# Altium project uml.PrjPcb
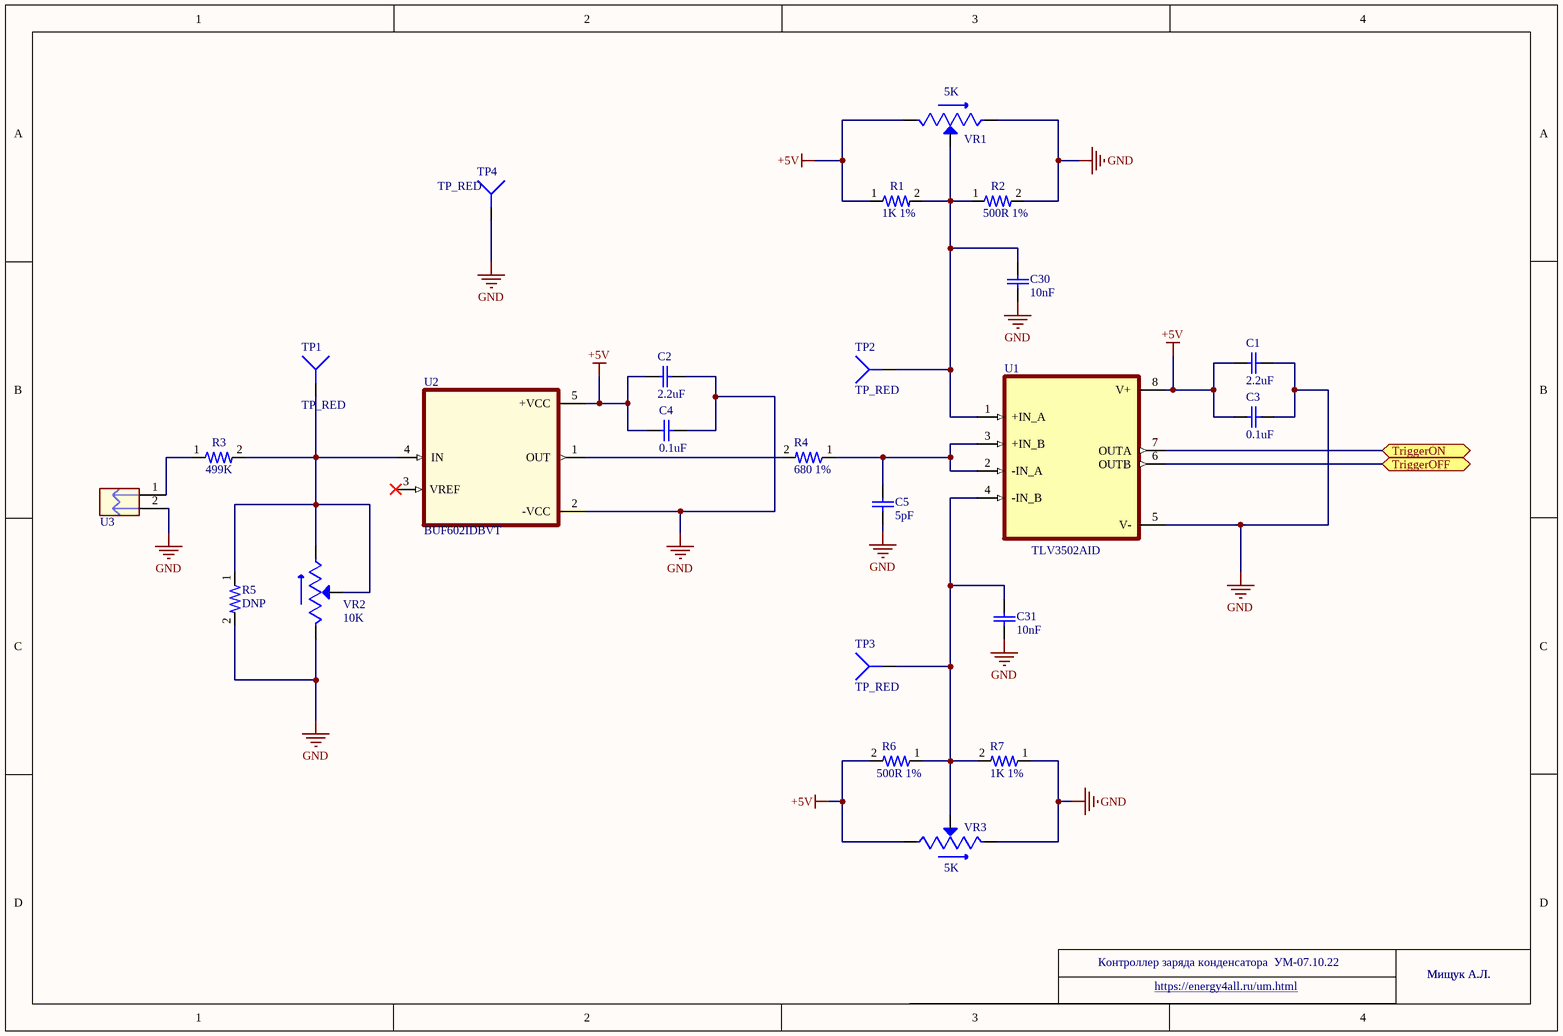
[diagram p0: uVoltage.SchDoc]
6 sheets, 99 parts. Net scope: flat (ports and power ports of the same name join across sheets).
Board file: uml.PcbDoc
Sheets:
  uVoltage.SchDoc
  lockgen.SchDoc
  lock.SchDoc
  uDelay.SchDoc
  uPower.SchDoc
  uSupply.SchDoc

## Sheet uVoltage.SchDoc
size A4; SheetNumber: 1; SheetTotal: 7

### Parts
C1  2.2uF  [CAP_0603]
C2  2.2uF  [CAP_0603]
C3  0.1uF  [CAP_0603]
C4  0.1uF  [CAP_0603]
C5  5pF  [CAP_0603]
C30  10nF  [CAP_0603]
C31  10nF  [CAP_0603]
R1  1K 1%  [RESC1608X50N]
R2  500R 1%  [RESC1608X50N]
R3  499K  [RES_2512]
R4  680 1%  [RESC1608X50N]
R5  DNP  [RESC1608X50N]
R6  500R 1%  [RESC1608X50N]
R7  1K 1%  [RESC1608X50N]
TP1  TP_RED  [TP_RED]
TP2  TP_RED  [TP_RED]
TP3  TP_RED  [TP_RED]
TP4  TP_RED  [TP_RED]
U1  TLV3502AID  [TLV3502AID]
U2  BUF602IDBVT  [BUF602IDBVT]
U3  DG129-5.0-02P  [DG129-5.0-02P]  (value not drawn)
VR1  5K  [TRIM_3296W-1-250]
VR2  10K  [TRIM_3296W-1-250]
VR3  5K  [TRIM_3296W-1-250]

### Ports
TriggerOFF (bidir), TriggerON (bidir)

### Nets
+5V: C1.1 C2.1 C3.1 C4.1 R1.1 R6.2 U1.8(V+) U2.5(+VCC) VR1.1(CCW) VR3.1(CCW)
GND: C1.2 C2.2 C3.2 C4.2 C5.2 C30.2 C31.2 R2.2 R5.2 R7.1 TP4.1 U1.5(V-) U2.2(-VCC) U3.2 VR1.3(CW) VR2.1(CCW) VR3.3(CW)
NetC5_1: C5.1 R4.1 U1.2(-IN_A) U1.3(+IN_B)
NetC30_1: C30.1 R1.2 R2.1 TP2.1 U1.1(+IN_A) VR1.2(WIPER)
NetC31_1: C31.1 R6.1 R7.2 TP3.1 U1.4(-IN_B) VR3.2(WIPER)
NetR3_1: R3.1 U3.1
NetR3_2: R3.2 R5.1 TP1.1 U2.4(IN) VR2.2(WIPER) VR2.3(CW)
NetR4_2: R4.2 U2.1(OUT)
NetU1_6: U1.6(OUTB) ; port TriggerOFF
NetU1_7: U1.7(OUTA) ; port TriggerON

Not connected (* = marked no-connect by the designer): U2 3(VREF)*

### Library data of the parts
C1-C5 C30 C31 = CAP_0603
R1 R2 R4-R7 = RES_0603: 1% 0.1W; MP: 1-2176071-4
R3 = RES_2512: 2512 1% 1W; MP: 1-2176071-4
TP1-TP4 = TP_RED: RF EMI Absorbing Sheet - Polyurethane Foam 24.000 (609.60mm) X 24.000 (609.60mm) X 0.252 (6.40mm); MF: Aeroflex; MP: 5010
U1 = TLV3502AID: 4.5ns Rail-to-Rail Comparator; MF: Texas Instruments
U2 = BUF602IDBVT: 1000MHz,Wide Bandwidth, High-Speed, Closed Loop Buffer 5-SOT-23 -45 to 85; MF: Texas Instruments
U3 = DG129-5.0-02P: DG129-5.0-02P-14-00A(H)
VR1-VR3 = 3296W-1-250: 25 Ohms 0.5W, 1/2W PC Pins Through Hole Trimmer Potentiometer Cermet 25 Turn Top Adjustment; MF: Bourns

## Sheet lockgen.SchDoc
size A4; Organization: Altium Limited; Address1: L3, 12a Rodborough Rd; Address2: Frenchs Forest; Address3: NSW; Address4: Australia 2086
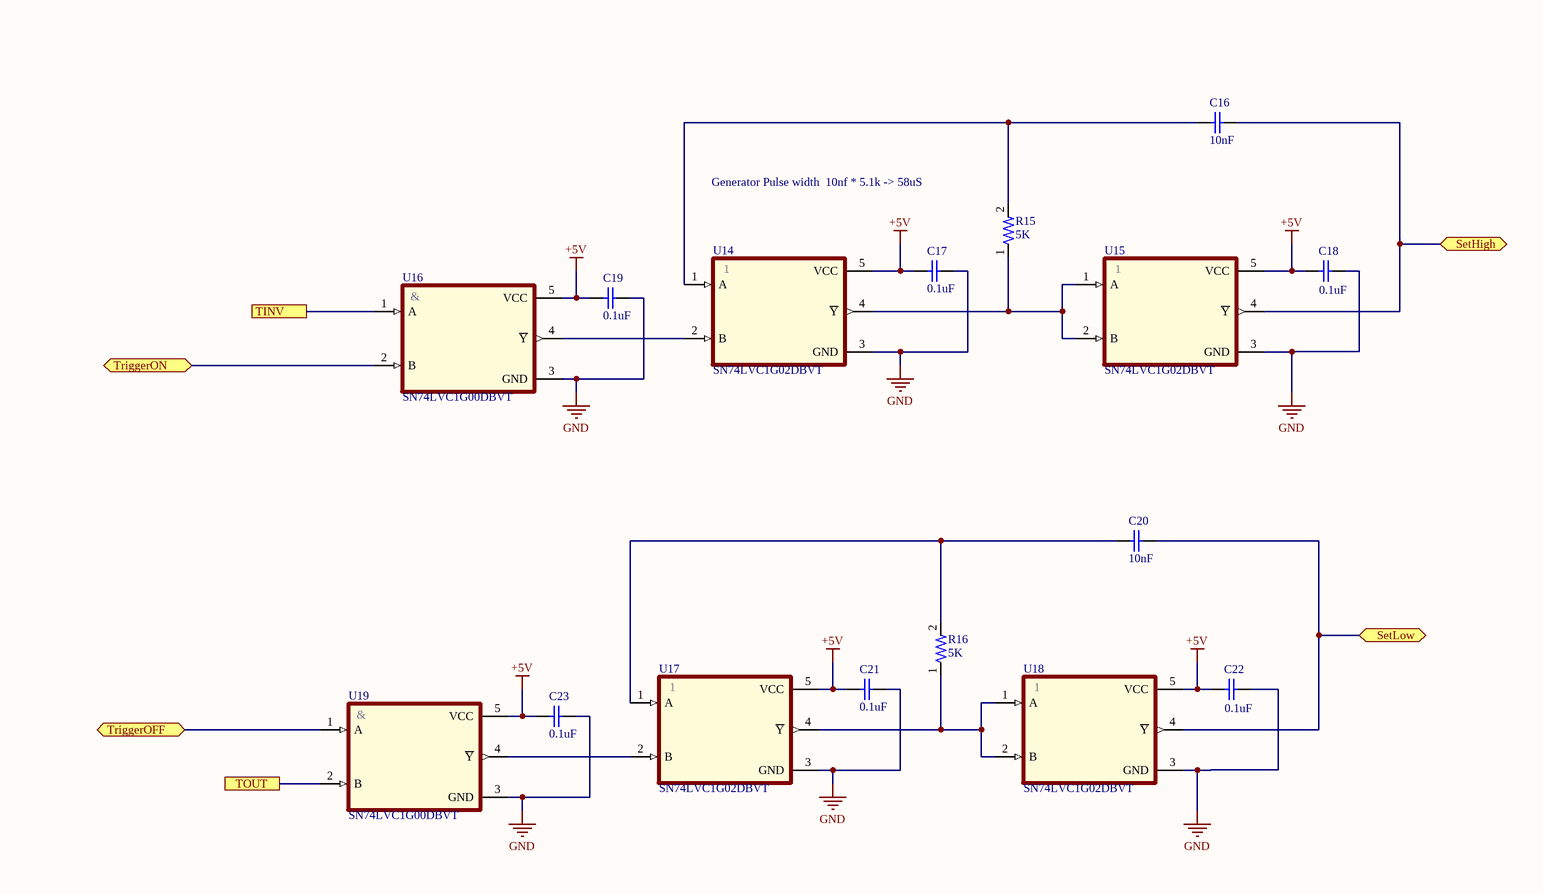
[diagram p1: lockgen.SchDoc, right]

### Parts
C16  10nF  [CAP_0603]
C17  0.1uF  [CAP_0603]
C18  0.1uF  [CAP_0603]
C19  0.1uF  [CAP_0603]
C20  10nF  [CAP_0603]
C21  0.1uF  [CAP_0603]
C22  0.1uF  [CAP_0603]
C23  0.1uF  [CAP_0603]
R15  5K  [RESC1608X50N]
R16  5K  [RESC1608X50N]
U14  SN74LVC1G02DBVT  [SOT23-5]
U15  SN74LVC1G02DBVT  [SOT23-5]
U16  SN74LVC1G00DBVT  [SOT23-5]
U17  SN74LVC1G02DBVT  [SOT23-5]
U18  SN74LVC1G02DBVT  [SOT23-5]
U19  SN74LVC1G00DBVT  [SOT23-5]

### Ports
SetHigh (bidir), SetLow (bidir), TINV, TOUT, TriggerOFF (bidir), TriggerON (bidir)

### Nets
+5V: C17.2 C18.2 C19.2 C21.2 C22.2 C23.2 U14.5(VCC) U15.5(VCC) U16.5(VCC) U17.5(VCC) U18.5(VCC) U19.5(VCC)
GND: C17.1 C18.1 C19.1 C21.1 C22.1 C23.1 U14.3(GND) U15.3(GND) U16.3(GND) U17.3(GND) U18.3(GND) U19.3(GND)
NetC16_1: C16.1 R15.2 U14.1(A)
NetC16_2: C16.2 U15.4(~{Y}) ; port SetHigh
NetC20_1: C20.1 R16.2 U17.1(A)
NetC20_2: C20.2 U18.4(~{Y}) ; port SetLow
NetJP4_3: U19.2(B) ; port TOUT
NetJP5_1: U16.1(A) ; port TINV
NetR15_1: R15.1 U14.4(~{Y}) U15.1(A) U15.2(B)
NetR16_1: R16.1 U17.4(~{Y}) U18.1(A) U18.2(B)
NetU1_6: U19.1(A) ; port TriggerOFF
NetU1_7: U16.2(B) ; port TriggerON
NetU14_2: U14.2(B) U16.4(~{Y})
NetU17_2: U17.2(B) U19.4(~{Y})

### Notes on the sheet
- (near R15) Generator Pulse width  10nf * 5.1k -> 58uS

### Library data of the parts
C16-C23 = CAP_0603
R15 R16 = RES_0603: 1% 0.1W; MP: 1-2176071-4
U14 U15 U17 U18 = SN74LVC1G02DBVT: NOR IC 1 canal SOT-23-5; MF: Texas Instruments
U16 U19 = SN74LVC1G00DBVT: NAND IC 1 canal SOT-23-5; MF: Texas Instruments

## Sheet lock.SchDoc
size A4; Organization: Altium Limited; Address1: L3, 12a Rodborough Rd; Address2: Frenchs Forest; Address3: NSW; Address4: Australia 2086
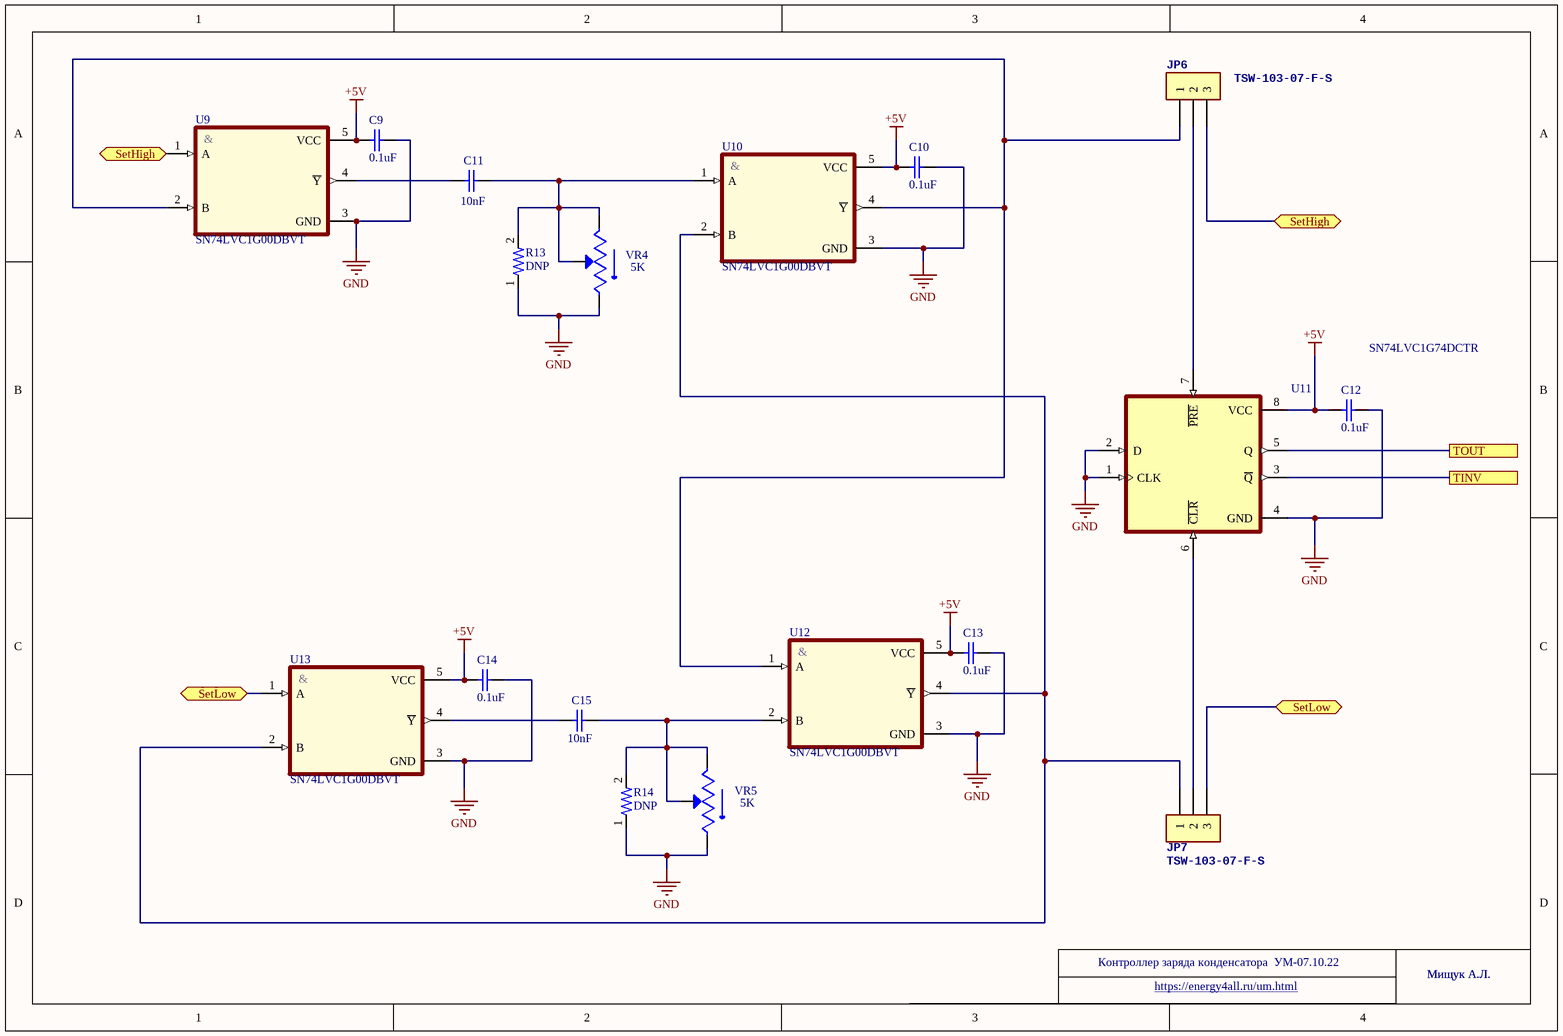
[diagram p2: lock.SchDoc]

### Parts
C9  0.1uF  [CAP_0603]
C10  0.1uF  [CAP_0603]
C11  10nF  [CAP_0603]
C12  0.1uF  [CAP_0603]
C13  0.1uF  [CAP_0603]
C14  0.1uF  [CAP_0603]
C15  10nF  [CAP_0603]
JP6  TSW-103-07-F-S  [TSW-103-07-F-S]
JP7  TSW-103-07-F-S  [TSW-103-07-F-S]
R13  DNP  [RESC1608X50N]
R14  DNP  [RESC1608X50N]
U9  SN74LVC1G00DBVT  [SOT23-5]
U10  SN74LVC1G00DBVT  [SOT23-5]
U11  SN74LVC1G74DCTR  [SN74LVC1G74DCTR]
U12  SN74LVC1G00DBVT  [SOT23-5]
U13  SN74LVC1G00DBVT  [SOT23-5]
VR4  5K  [TRIM_3296W-1-250]
VR5  5K  [TRIM_3296W-1-250]

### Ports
SetHigh (bidir), SetLow (bidir), TINV, TOUT

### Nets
+5V: C9.2 C10.2 C12.2 C13.2 C14.2 U9.5(VCC) U10.5(VCC) U11.8(VCC) U12.5(VCC) U13.5(VCC)
GND: C9.1 C10.1 C12.1 C13.1 C14.1 R13.1 R14.1 U9.3(GND) U10.3(GND) U11.1(CLK) U11.2(D) U11.4(GND) U12.3(GND) U13.3(GND) VR4.3(CW) VR5.3(CW)
NetC11_1: C11.1 R13.2 U10.1(A) VR4.1(CCW) VR4.2(WIPER)
NetC11_2: C11.2 U9.4(~{Y})
NetC15_1: C15.1 R14.2 U12.2(B) VR5.1(CCW) VR5.2(WIPER)
NetC15_2: C15.2 U13.4(~{Y})
NetC16_2: JP6.3 U9.1(A) ; port SetHigh
NetC20_2: JP7.3 U13.1(A) ; port SetLow
NetJP4_3: U11.5(Q) ; port TOUT
NetJP5_1: U11.3(~{Q}) ; port TINV
NetJP6_1: JP6.1 U9.2(B) U10.4(~{Y}) U12.1(A)
NetJP6_2: JP6.2 U11.7(~{PRE})
NetJP7_1: JP7.1 U10.2(B) U12.4(~{Y}) U13.2(B)
NetJP7_2: JP7.2 U11.6(~{CLR})

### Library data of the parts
C9-C15 = CAP_0603
R13 R14 = RES_0603: 1% 0.1W; MP: 1-2176071-4
U9 U10 U12 U13 = SN74LVC1G00DBVT: as U16 on sheet lockgen
U11 = SN74LVC1G74DCTR: Single Positive-Edge-Triggered D-Type Flip-Flop With Clear and Preset 8-SM8 -40 to 125; MF: Texas Instruments
VR4 VR5 = 3296W-1-250: as VR1 on sheet uVoltage

## Sheet uDelay.SchDoc
size A4; SheetNumber: 1; SheetTotal: 7
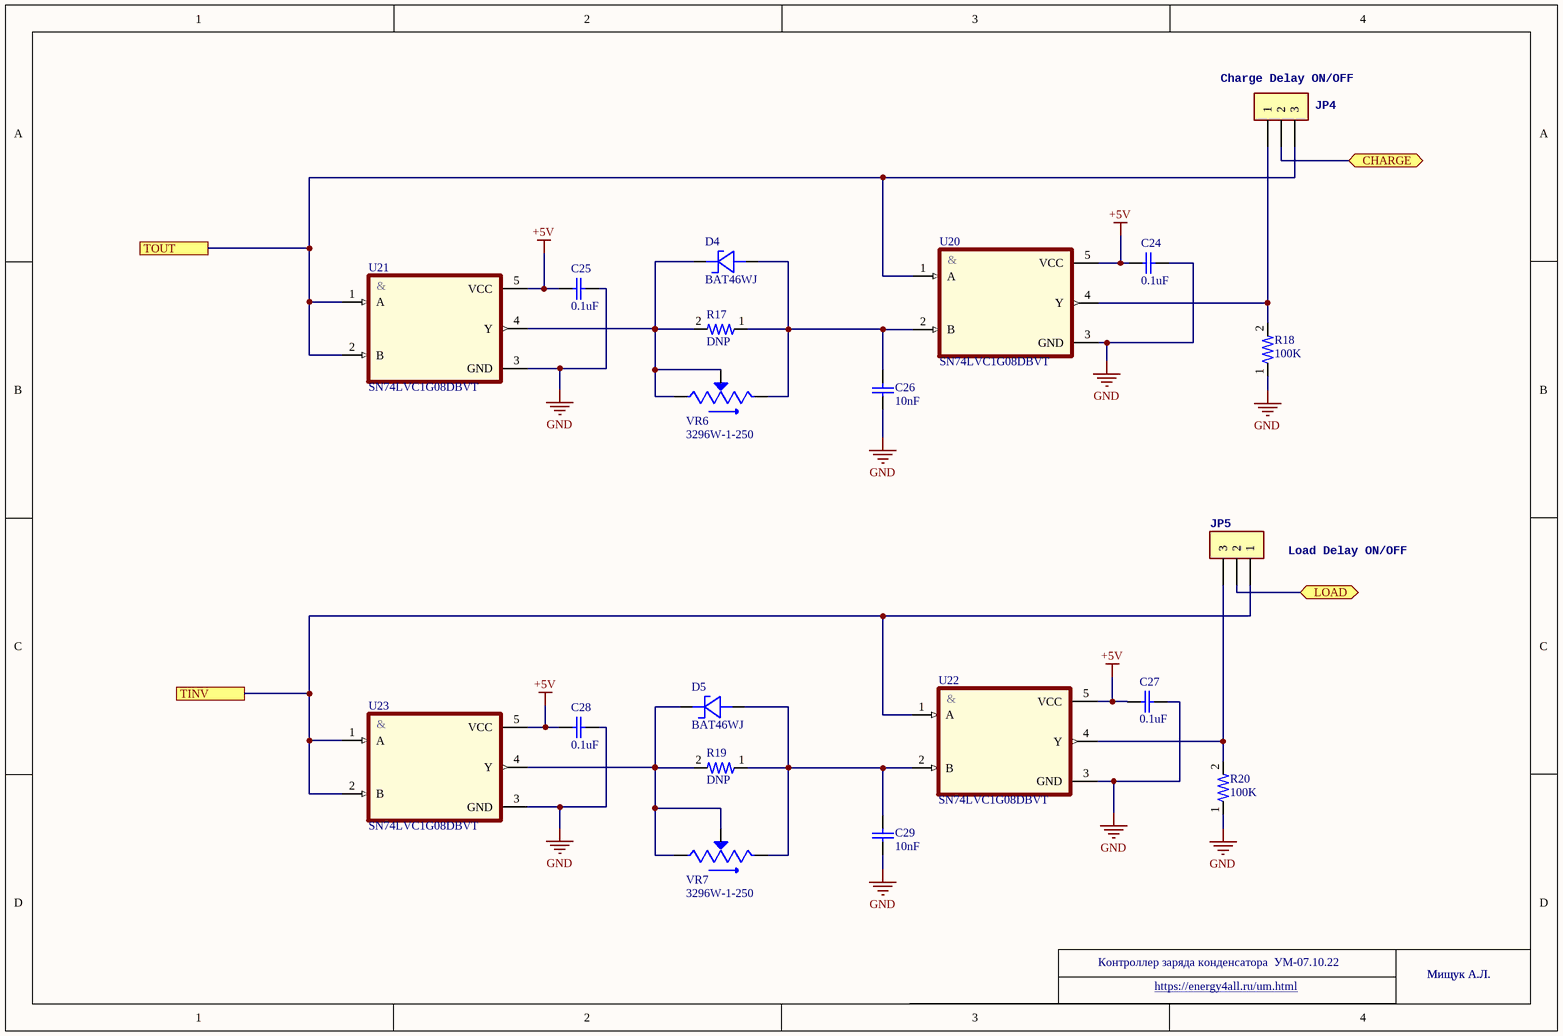
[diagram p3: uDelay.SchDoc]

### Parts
C24  0.1uF  [CAP_0603]
C25  0.1uF  [CAP_0603]
C26  10nF  [CAP_0805]
C27  0.1uF  [CAP_0603]
C28  0.1uF  [CAP_0603]
C29  10nF  [CAP_0805]
D4  BAT46WJ  [BAT46WJ]
D5  BAT46WJ  [BAT46WJ]
JP4  Charge Delay ON/OFF  [TSW-103-07-F-S]
JP5  Load Delay ON/OFF  [TSW-103-07-F-S]
R17  DNP  [RESC1608X50N]
R18  100K  [RESC1608X50N]
R19  DNP  [RESC1608X50N]
R20  100K  [RESC1608X50N]
U20  SN74LVC1G08DBVT  [SOT23-5]
U21  SN74LVC1G08DBVT  [SOT23-5]
U22  SN74LVC1G08DBVT  [SOT23-5]
U23  SN74LVC1G08DBVT  [SOT23-5]
VR6  3296W-1-250  [TRIM_3296W-1-250]
VR7  3296W-1-250  [TRIM_3296W-1-250]

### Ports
CHARGE (bidir), LOAD (bidir), TINV, TOUT

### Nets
+5V: C24.1 C25.1 C27.1 C28.1 U20.5(VCC) U21.5(VCC) U22.5(VCC) U23.5(VCC)
GND: C24.2 C25.2 C26.1 C27.2 C28.2 C29.1 R18.1 R20.1 U20.3(GND) U21.3(GND) U22.3(GND) U23.3(GND)
NetC26_2: C26.2 D4.A R17.1 U20.2(B) VR6.3(CW)
NetC29_2: C29.2 D5.A R19.1 U22.2(B) VR7.3(CW)
NetD4_C: D4.C R17.2 U21.4(Y) VR6.1(CCW) VR6.2(WIPER)
NetD5_C: D5.C R19.2 U23.4(Y) VR7.1(CCW) VR7.2(WIPER)
NetJP2_1: JP4.2 ; port CHARGE
NetJP3_1: JP5.2 ; port LOAD
NetJP4_1: JP4.1 R18.2 U20.4(Y)
NetJP4_3: JP4.3 U20.1(A) U21.1(A) U21.2(B) ; port TOUT
NetJP5_1: JP5.1 U22.1(A) U23.1(A) U23.2(B) ; port TINV
NetJP5_3: JP5.3 R20.2 U22.4(Y)

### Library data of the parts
C24 C25 C27 C28 = CAP_0603
C26 C29 = CAP_0805
D4 D5 = BAT46WJ: Diode Schottky 100V 250mA (DC) Surface Mount SOD-323F; MF: NXP Semiconductors
JP4 JP5 = TSW-103-07-F-S
R17-R20 = RES_0603: 1% 0.1W; MP: 1-2176071-4
U20-U23 = SN74LVC1G08DBVT: AND IC 1 chanal SOT-23-5; MF: Texas Instruments
VR6 VR7 = 3296W-1-250: as VR1 on sheet uVoltage

## Sheet uPower.SchDoc
size A4; SheetNumber: 1; SheetTotal: 7
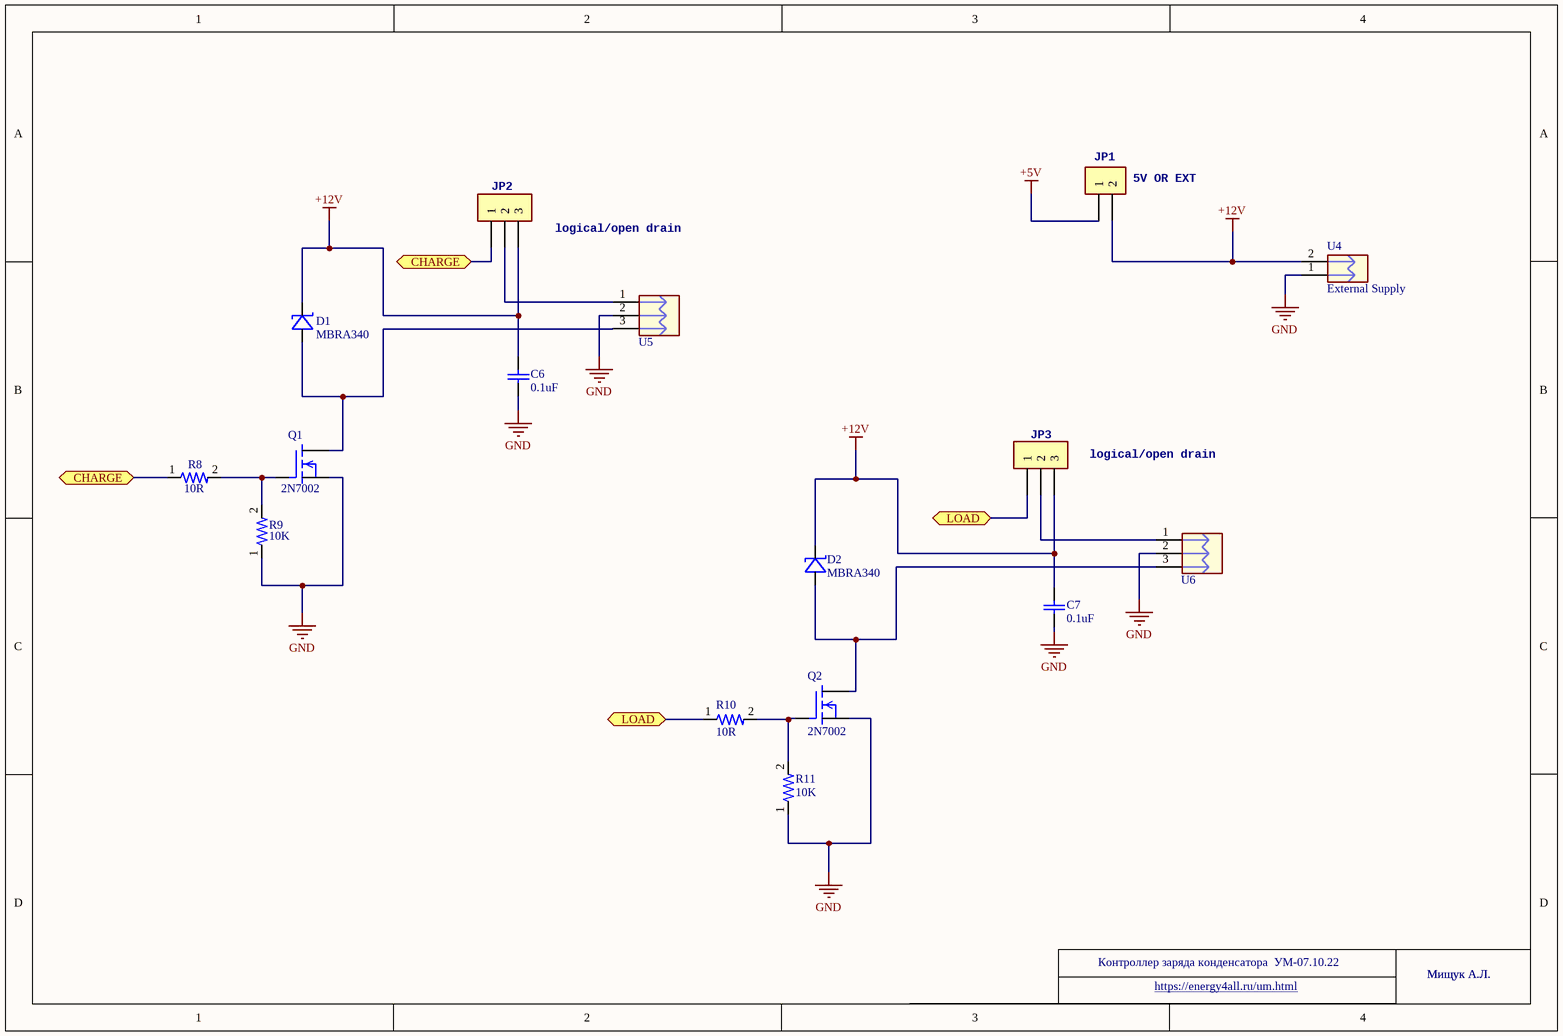
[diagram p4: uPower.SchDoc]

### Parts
C6  0.1uF  [CAP_1206]
C7  0.1uF  [CAP_1206]
D1  MBRA340  [MBRA340]
D2  MBRA340  [MBRA340]
JP1  5V OR EXT  [TSW-102-07-F-S]
JP2  logical/open drain  [TSW-103-07-F-S]
JP3  logical/open drain  [TSW-103-07-F-S]
Q1  2N7002  [2N7002]
Q2  2N7002  [2N7002]
R8  10R  [RESC1608X50N]
R9  10K  [RESC1608X50N]
R10  10R  [RESC1608X50N]
R11  10K  [RESC1608X50N]
U4  External Supply  [DG129-5.0-02P]
U5  DG129-5.0-03P  [DG129-5.0-03P]  (value not drawn)
U6  DG129-5.0-03P  [DG129-5.0-03P]  (value not drawn)

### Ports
CHARGE (bidir), LOAD (bidir)

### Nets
+5V: JP1.1
+12V: C6.2 C7.2 D1.C D2.C JP1.2 JP2.3 JP3.3 U4.2
GND: C6.1 C7.1 Q1.2(S) Q2.2(S) R9.1 R11.1 U4.1 U5.2 U6.2
NetD1_A: D1.A Q1.3(D) U5.3
NetD2_A: D2.A Q2.3(D) U6.3
NetJP2_1: JP2.1 R8.1 ; port CHARGE
NetJP2_2: JP2.2 U5.1
NetJP3_1: JP3.1 R10.1 ; port LOAD
NetJP3_2: JP3.2 U6.1
NetQ1_1: Q1.1(G) R8.2 R9.2
NetQ2_1: Q2.1(G) R10.2 R11.2

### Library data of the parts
C6 C7 = CAP_1206
D1 D2 = MBRA340: DIODE, SCHOTTKY, 3A, 40V, SMA; MF: ON Semiconductor
JP1 = TSW-102-07-F-S
JP2 JP3 = TSW-103-07-F-S
Q1 Q2 = 2N7002: N-Channel 60V 200mA _Tc_ 350mW _Tc_ Surface Mount SOT-23-3; MF: STMicroelectronics
R8-R11 = RES_0603: 1% 0.1W; MP: 1-2176071-4
U4 = DG129-5.0-02P: DG129-5.0-02P-14-00A(H)
U5 U6 = DG129-5.0-03P: DG129-5.0-03P-14-00AH

## Sheet uSupply.SchDoc
size A4; SheetNumber: 1; SheetTotal: 7
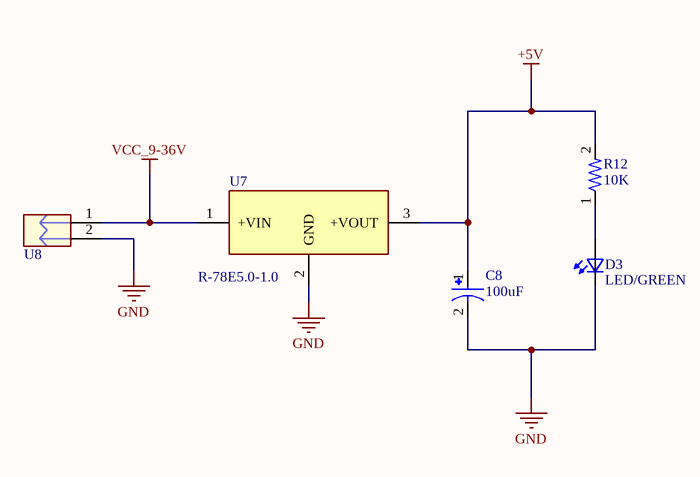
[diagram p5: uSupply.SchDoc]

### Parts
C8  100uF  [CAP_TYPE_D]
D3  LED/GREEN  [LED_0603]
R12  10K  [RESC1608X50N]
U7  R-78E5.0-1.0  [R-78E5.0-1.0]
U8  DG129-5.0-02P  [DG129-5.0-02P]  (value not drawn)

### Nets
+5V: C8.1 R12.2 U7.3(+VOUT)
GND: C8.2 D3.1(K1) U7.2(GND) U8.2
VCC_9-36V: U7.1(+VIN) U8.1
NetD3_2: D3.2(A2) R12.1

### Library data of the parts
C8 = CAP_TYPE_D: MP: 25TQC15MV
D3 = LED_0603: Blue 470nm LED Indication - Discrete 3.3V 0603 _1608 Metric_; MP: LTST-S270TBKT; MF: Lite-On Inc.
R12 = RES_0603: 1% 0.1W; MP: 1-2176071-4
U7 = R-78E5.0-1.0: 1A DC/DC-Converter SIP3; MF: Recom Power
U8 = DG129-5.0-02P: DG129-5.0-02P-14-00A(H)

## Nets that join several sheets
+5V: uVoltage (10 pins), lockgen (12 pins), lock (10 pins), uDelay (8 pins), uPower (JP1.1), uSupply (C8.1 R12.2 U7.3)
GND: uVoltage (17 pins), lockgen (12 pins), lock (16 pins), uDelay (12 pins), uPower (9 pins), uSupply (C8.2 D3.1 U7.2 U8.2)
NetC16_2: lockgen (C16.2 U15.4), lock (JP6.3 U9.1)
NetC20_2: lockgen (C20.2 U18.4), lock (JP7.3 U13.1)
NetJP2_1: uDelay (JP4.2), uPower (JP2.1 R8.1)
NetJP3_1: uDelay (JP5.2), uPower (JP3.1 R10.1)
NetJP4_3: lockgen (U19.2), lock (U11.5), uDelay (JP4.3 U20.1 U21.1 U21.2)
NetJP5_1: lockgen (U16.1), lock (U11.3), uDelay (JP5.1 U22.1 U23.1 U23.2)
NetU1_6: uVoltage (U1.6), lockgen (U19.1)
NetU1_7: uVoltage (U1.7), lockgen (U16.2)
